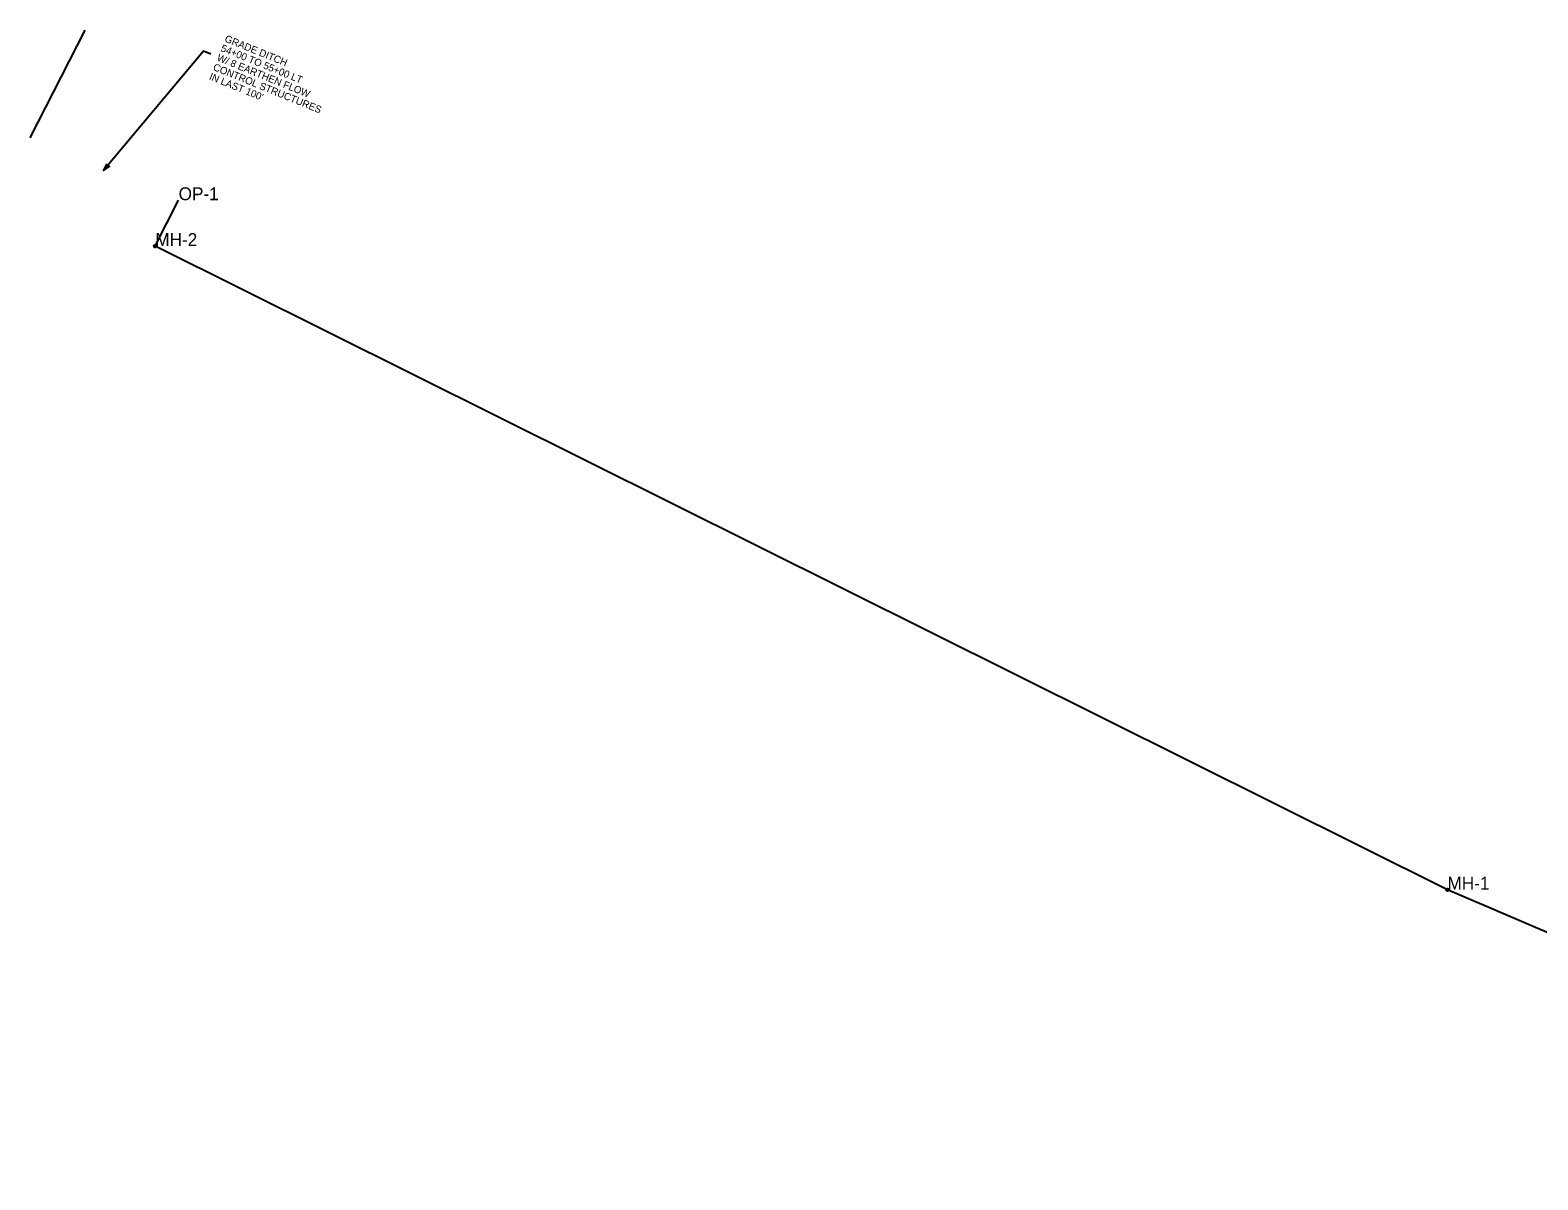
# Model space of a CAD drawing. Extents: x 2165744 to 2171481, y 206867 to 209489.
# Drawn here: x 2165744 to 2166683, y 208773 to 209489 of the extents above; entities that cross this region are included whole.
import ezdxf

# ---------------------------------------------------------------- set-up
doc = ezdxf.new("R2010")
doc.units = 0
for name, color, linetype in [('RD_PD_DR_Inlet', 7, 'Continuous'), ('RD_PD_DR_Inlet_TX', 7, 'Continuous'), ('RD_PD_DR_Pipe', 7, 'Continuous'), ('RD_TX_Drainage', 7, 'Continuous')]:
    doc.layers.add(name, color=color, linetype=linetype)

msp = doc.modelspace()

# ---------------------------------------------------------------- linework, layer by layer
at = {"layer": 'RD_PD_DR_Inlet'}
for p, q in [((2165821.3, 209354.95), (2165821.3, 209354.95)), ((2165821.56, 209354.13), (2165821.56, 209354.13)), ((2165821.56, 209354.13), (2165821.56, 209354.13)), ((2165821.84, 209354.67), (2165821.84, 209354.67)), ((2165821.84, 209354.67), (2165821.84, 209354.67)), ((2165822.12, 209355.22), (2165822.12, 209355.22)), ((2165822.12, 209355.22), (2165822.12, 209355.22)), ((2165822.39, 209354.39), (2165822.39, 209354.39)), ((2166626.15, 208953.89), (2166626.15, 208953.89)), ((2166626.44, 208953.08), (2166626.44, 208953.08)), ((2166626.44, 208953.08), (2166626.44, 208953.08)), ((2166626.7, 208953.64), (2166626.7, 208953.64)), ((2166626.7, 208953.64), (2166626.7, 208953.64)), ((2166626.96, 208954.19), (2166626.96, 208954.19)), ((2166626.96, 208954.19), (2166626.96, 208954.19)), ((2166627.25, 208953.38), (2166627.25, 208953.38))]:
    msp.add_line(p, q, dxfattribs=at)
for centre, radius in [((2165821.84, 209354.67), 0.833), ((2165821.84, 209354.67), 0.611), ((2166626.7, 208953.64), 0.833), ((2166626.7, 208953.64), 0.611)]:
    msp.add_circle(centre, radius, dxfattribs=at)
at = {"layer": 'RD_PD_DR_Pipe'}
for p, q in [((2165743.91, 209421.99), (2165778.14, 209489.16)), ((2165821.84, 209354.67), (2165836.39, 209383.22)), ((2166626.69, 208953.62), (2165821.84, 209354.67)), ((2167046.63, 208772.86), (2166626.69, 208953.62))]:
    msp.add_line(p, q, dxfattribs=at)
at = {"layer": 'RD_TX_Drainage'}
msp.add_lwpolyline([(2165856.51, 209474.12), (2165851.82, 209476.03), (2165789.67, 209401.66)], dxfattribs=at)
msp.add_lwpolyline([(2165791.56, 209405.74), (2165789.67, 209401.66), (2165793.35, 209404.25)], close=True, dxfattribs=at)

# ---------------------------------------------------------------- texts
at = {"layer": 'RD_PD_DR_Inlet'}
msp.add_text('OP', height=0.001, rotation=338.46434, dxfattribs=at).set_placement((2165836.39, 209383.22))
at = {"layer": 'RD_PD_DR_Inlet_TX'}
for s, p in [('OP-1', (2165836.39, 209383.22)), ('MH-2', (2165821.85, 209354.68)), ('MH-1', (2166626.71, 208953.67))]:
    msp.add_text(s, height=8, dxfattribs=at).set_placement(p)
at = {"layer": 'RD_TX_Drainage'}
for s, p in [('GRADE DITCH', (2165864.64, 209482.15)), ('W/ 8 EARTHEN FLOW', (2165859.83, 209470.34)), ('54+00 TO 55+00 LT', (2165862.23, 209476.24)), ('CONTROL STRUCTURES', (2165857.42, 209464.43)), ("IN LAST 100'", (2165855.02, 209458.53))]:
    msp.add_text(s, height=4.5, rotation=337.83882, dxfattribs=at).set_placement(p)

doc.saveas('drawing.dxf')
